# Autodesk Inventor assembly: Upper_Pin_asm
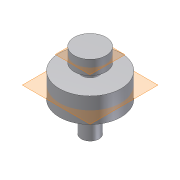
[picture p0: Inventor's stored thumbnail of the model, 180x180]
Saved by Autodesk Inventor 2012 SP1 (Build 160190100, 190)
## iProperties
Created: 2006-09
Part Number: Upper_Pin_asm
Document SubType Name: Assembly
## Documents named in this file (3)
- D:\Backup\CMU Work Temp\XX\Inv2012DynSim\Sub-Assemblies\Upper_Pin_asm.iam
- D:\Backup\CMU Work Temp\XX\Inv2012DynSim\Parts\Pin.ipt
- D:\Backup\CMU Work Temp\XX\Inv2012DynSim\Parts\Pin_small.ipt
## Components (2 placed, 2 different names)
1. Pin:1 — Mate:2, Mate:1
2. Pin_small:1 — Mate:2, Mate:1
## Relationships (2: Mate 2)
- Mate:2: Pin:1 ↔ Pin_small:1
- Mate:1: Pin:1 ↔ Pin_small:1
